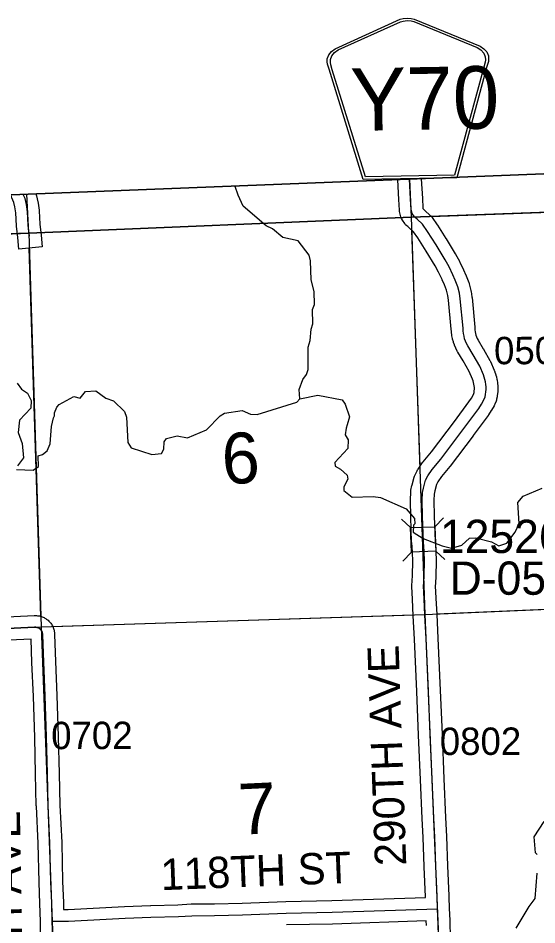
# Model space of a CAD drawing. Extents: x 128.7 to 185.5, y -21.4 to 12.6.
# Drawn here: x 151.741 to 153.067, y 3.118 to 5.436 of the extents above; entities that cross this region are included whole.
import ezdxf

# ---------------------------------------------------------------- set-up
doc = ezdxf.new("R2010")
doc.units = 0
for name, color, linetype in [('tdCoClipBndry', 7, 'Continuous'), ('tdCoCoBndry', 7, 'Continuous'), ('tdCoCoBndryPart', 7, 'Continuous'), ('tdCoHydroRiver', 7, 'Continuous'), ('tdCoSecRdNmbr', 7, 'Continuous'), ('tdCoSecRdTxt', 7, 'Continuous'), ('tdCoSecRteBand', 7, 'Continuous'), ('tdCoSecRteCL', 7, 'Continuous'), ('tdCoSectLine', 7, 'Continuous'), ('tdCoSectLinePart', 7, 'Continuous'), ('tdCoSectNmbr', 7, 'Continuous'), ('tdCoShieldCoRte', 7, 'Continuous'), ('tdCoStrucSec', 7, 'Continuous'), ('tdCoStrucSecCoName', 7, 'Continuous'), ('tdCoStrucSecFHWANum', 7, 'Continuous'), ('tdCoSurfGravel', 7, 'Continuous'), ('tdCoTwpBndry', 7, 'Continuous'), ('tdCoTwpBndryShd', 7, 'Continuous')]:
    doc.layers.add(name, color=color, linetype=linetype)

msp = doc.modelspace()

# ---------------------------------------------------------------- linework, layer by layer
at = {"layer": 'tdCoClipBndry'}
msp.add_lwpolyline([(134.0612, -7.7025), (133.8962, -2.6807), (133.6887, 4.3446), (133.6938, 4.3792), (133.7053, 4.4028), (133.7226, 4.4226), (133.7445, 4.4372), (133.7868, 4.4475), (134.771, 4.4649), (135.7559, 4.4935), (136.7866, 4.5129), (139.7725, 4.5879), (146.7594, 4.806), (147.7608, 4.8492), (149.7557, 4.9088), (150.75, 4.946), (153.7332, 5.0633)], dxfattribs=at)
at = {"layer": 'tdCoCoBndry'}
for p, q in [((152.7457, 4.9271), (153.7304, 4.9634)), ((153.7304, 4.9634), (152.7457, 4.9271)), ((151.7687, 4.8866), (152.7457, 4.9271)), ((152.7457, 4.9271), (151.7687, 4.8866)), ((150.7629, 4.8466), (151.7687, 4.8866)), ((151.7687, 4.8866), (150.7629, 4.8466))]:
    msp.add_line(p, q, dxfattribs=at)
for points in [[(153.7332, 5.0633), (150.75, 4.946), (149.7557, 4.9088), (147.7608, 4.8492), (146.7594, 4.806), (139.7725, 4.5879), (136.7866, 4.5129)], [(136.7888, 4.4129), (137.7724, 4.4375), (137.7858, 4.438), (138.7769, 4.4617), (139.7753, 4.488), (140.7687, 4.5163), (141.7663, 4.5476), (142.7677, 4.58), (143.7742, 4.6139), (144.7719, 4.6433), (145.7753, 4.6779), (146.7631, 4.7061), (147.7638, 4.7493), (148.7588, 4.7767), (149.759, 4.8089), (150.7538, 4.8461), (150.7626, 4.8466), (151.7683, 4.8866), (152.7453, 4.9271), (153.73, 4.9634)], [(136.7891, 4.4129), (137.7728, 4.4375), (137.7862, 4.438), (138.7773, 4.4617), (139.7757, 4.488), (140.769, 4.5163), (141.7667, 4.5476), (142.7681, 4.58), (143.7746, 4.6139), (144.7722, 4.6433), (145.7757, 4.6779), (146.7635, 4.7061), (147.7642, 4.7493), (148.7592, 4.7767), (149.7594, 4.8089), (150.7542, 4.8461), (150.7629, 4.8466), (151.7687, 4.8866), (152.7457, 4.9271), (153.7304, 4.9634)], [(136.7891, 4.4129), (137.7728, 4.4375), (137.7862, 4.438), (138.7773, 4.4617), (139.7757, 4.488), (140.769, 4.5163), (141.7667, 4.5476), (142.7681, 4.58), (143.7746, 4.6139), (144.7722, 4.6433), (145.7757, 4.6779), (146.7635, 4.7061), (147.7642, 4.7493), (148.7592, 4.7767), (149.7594, 4.8089), (150.7542, 4.8461), (150.7629, 4.8466), (151.7687, 4.8866), (152.7457, 4.9271), (153.7304, 4.9634)]]:
    msp.add_lwpolyline(points, dxfattribs=at)
at = {"layer": 'tdCoCoBndryPart'}
for points in [[(152.7968, 4.929), (153.73, 4.9634), (153.7375, 4.9634), (154.1359, 4.9808)], [(151.7989, 4.8879), (152.7199, 4.926)]]:
    msp.add_lwpolyline(points, dxfattribs=at)
at = {"layer": 'tdCoHydroRiver'}
for points in [[(152.4613, 4.4629), (152.4589, 4.4865), (152.4691, 4.5121), (152.4781, 4.525), (152.4824, 4.5378), (152.4821, 4.5946), (152.4878, 4.6122), (152.49, 4.6407), (152.4942, 4.655), (152.493, 4.6913), (152.4988, 4.7041), (152.4977, 4.7373), (152.4904, 4.767), (152.4887, 4.8159), (152.4851, 4.83), (152.457, 4.8669), (152.4172, 4.875), (152.3912, 4.8978), (152.3752, 4.9051), (152.3166, 4.9552), (152.303, 4.9832), (152.2955, 5.0058)], [(151.7384, 4.5029), (151.75, 4.4875), (151.7646, 4.477), (151.7747, 4.4584), (151.7738, 4.4394), (151.7448, 4.4084), (151.7412, 4.3767), (151.7516, 4.3486), (151.7544, 4.3124), (151.7393, 4.2914)], [(151.7365, 4.2818), (151.7792, 4.2801), (151.7931, 4.2901), (151.7922, 4.3169), (151.8031, 4.3204), (151.8154, 4.3303), (151.8227, 4.3479), (151.8259, 4.3922), (151.8315, 4.4145), (151.8344, 4.4194), (151.8342, 4.4272), (151.84, 4.4417), (151.8461, 4.4482), (151.8833, 4.4684), (151.8992, 4.4642), (151.9128, 4.482), (151.9396, 4.4829), (151.9655, 4.4649), (151.9847, 4.4576), (152.0125, 4.4302), (152.0177, 4.4161), (152.0215, 4.3516), (152.0298, 4.3376), (152.0825, 4.3205), (152.1077, 4.3229), (152.1136, 4.3342), (152.1146, 4.3532), (152.1206, 4.3613), (152.1472, 4.3685), (152.1742, 4.3631), (152.2225, 4.3837), (152.2575, 4.4196), (152.2684, 4.4263), (152.3139, 4.4326), (152.3348, 4.4238), (152.3522, 4.4228), (152.4537, 4.4547), (152.4613, 4.4629), (152.5068, 4.4723), (152.5688, 4.4602), (152.577, 4.4495), (152.5876, 4.4167), (152.582, 4.396), (152.5791, 4.388), (152.5766, 4.3705), (152.5849, 4.3582), (152.584, 4.336), (152.5505, 4.3002), (152.5509, 4.2907), (152.5653, 4.2833), (152.5816, 4.2681), (152.5836, 4.2571), (152.5732, 4.2378), (152.5735, 4.2283), (152.5946, 4.2117), (152.6482, 4.2135), (152.6673, 4.211), (152.733, 4.1817), (152.7543, 4.1572), (152.7548, 4.143), (152.7518, 4.1397), (152.7508, 4.1223), (152.7766, 4.1058), (152.8246, 4.0869), (152.8485, 4.0814), (152.8751, 4.0887), (152.895, 4.1067), (152.9108, 4.1072), (152.9506, 4.0976), (152.9699, 4.0872), (152.9902, 4.0942), (153.0113, 4.1217), (153.0216, 4.1442), (153.0182, 4.1978), (153.0318, 4.214), (153.0801, 4.2346)], [(153.0679, 3.298), (153.063, 3.3025), (153.06, 3.3435), (153.0855, 3.3823)], [(153.0143, 3.1099), (153.0472, 3.1647), (153.0622, 3.1857), (153.0679, 3.2506)]]:
    msp.add_lwpolyline(points, dxfattribs=at)
at = {"layer": 'tdCoSecRteBand'}
for points in [[(151.8574, 3.1575), (151.8691, 3.1576), (152.013, 3.1649), (152.0131, 3.1649), (152.0133, 3.165), (152.0794, 3.1677), (152.0796, 3.1677), (152.0799, 3.1677), (152.1493, 3.1694), (152.1832, 3.1716), (152.1841, 3.1716), (152.185, 3.1716), (152.2427, 3.1719), (152.3135, 3.1736), (152.425, 3.1778), (152.4252, 3.1778), (152.4255, 3.1778), (152.5427, 3.1803), (152.7821, 3.1881), (152.7821, 3.1897), (152.7786, 3.2667), (152.7786, 3.2668), (152.7786, 3.267), (152.7759, 3.3412), (152.7735, 3.3896), (152.7734, 3.3898), (152.7734, 3.3899), (152.7695, 3.489), (152.7646, 3.6031), (152.7646, 3.6032), (152.7646, 3.6032), (152.7599, 3.7144), (152.754, 3.8484), (152.7509, 3.9085), (152.7488, 3.9504), (152.7471, 3.9834), (152.747, 3.9854), (152.7471, 3.9875), (152.7479, 3.9959), (152.749, 4.0129), (152.7497, 4.0465), (152.7486, 4.0715), (152.7469, 4.095), (152.7468, 4.0956), (152.7468, 4.0961), (152.7446, 4.1612), (152.7446, 4.1614), (152.7446, 4.1615), (152.7436, 4.203), (152.7436, 4.2039), (152.7436, 4.2048), (152.7443, 4.2243), (152.7444, 4.2269), (152.745, 4.2294), (152.7474, 4.241), (152.7477, 4.242), (152.7479, 4.243), (152.7536, 4.2628), (152.7543, 4.2651), (152.7553, 4.2672), (152.7607, 4.2788), (152.7618, 4.2812), (152.7633, 4.2833), (152.7749, 4.2998), (152.7756, 4.3008), (152.7764, 4.3018), (152.7977, 4.3274), (152.8561, 4.4046), (152.8933, 4.4552), (152.8994, 4.4647), (152.9045, 4.4735), (152.9057, 4.4765), (152.9063, 4.4793), (152.9068, 4.4835), (152.9071, 4.4878), (152.9071, 4.492), (152.9067, 4.4963), (152.9061, 4.5005), (152.9052, 4.5047), (152.9039, 4.5088), (152.9023, 4.5131), (152.8939, 4.5328), (152.8785, 4.5598), (152.8646, 4.5823), (152.864, 4.5833), (152.8635, 4.5844), (152.8604, 4.5904), (152.86, 4.5913), (152.8595, 4.5923), (152.8569, 4.5985), (152.8565, 4.5995), (152.8562, 4.6005), (152.854, 4.6068), (152.8536, 4.6078), (152.8534, 4.6088), (152.8516, 4.6153), (152.8513, 4.6164), (152.8511, 4.6174), (152.8499, 4.624), (152.8497, 4.625), (152.8495, 4.6261), (152.8487, 4.6328), (152.8486, 4.6338), (152.8485, 4.6348), (152.8482, 4.641), (152.8414, 4.7151), (152.8396, 4.7266), (152.8362, 4.7404), (152.8308, 4.7543), (152.8247, 4.767), (152.8246, 4.7673), (152.8244, 4.7677), (152.8158, 4.7868), (152.8069, 4.8028), (152.7837, 4.8405), (152.7623, 4.874), (152.7518, 4.8896), (152.7405, 4.8996), (152.7367, 4.9031), (152.7345, 4.905), (152.7341, 4.9053), (152.7313, 4.9079), (152.7291, 4.9111), (152.7232, 4.92), (152.7206, 4.9239), (152.7193, 4.9285), (152.7166, 4.9381), (152.7156, 4.9414), (152.7155, 4.9449), (152.7143, 4.9721), (152.7116, 5.0231)], [(152.7715, 5.0255), (152.7742, 4.9752), (152.7742, 4.9751), (152.7742, 4.9749), (152.7753, 4.951), (152.7758, 4.9493), (152.7769, 4.9476), (152.7804, 4.9444), (152.7945, 4.9319), (152.7973, 4.9294), (152.7994, 4.9263), (152.8122, 4.9073), (152.8125, 4.9069), (152.8127, 4.9066), (152.8344, 4.8726), (152.8345, 4.8724), (152.8346, 4.8722), (152.8583, 4.8337), (152.8587, 4.8331), (152.859, 4.8326), (152.8689, 4.8148), (152.8695, 4.8137), (152.87, 4.8126), (152.8789, 4.7927), (152.8854, 4.7792), (152.886, 4.7781), (152.8864, 4.7769), (152.8928, 4.7601), (152.8935, 4.7585), (152.8939, 4.7567), (152.8981, 4.7399), (152.8984, 4.7387), (152.8986, 4.7374), (152.9009, 4.7236), (152.901, 4.7226), (152.9011, 4.7216), (152.908, 4.6459), (152.9081, 4.6453), (152.9081, 4.6447), (152.9084, 4.639), (152.909, 4.6344), (152.9098, 4.6299), (152.911, 4.6254), (152.9126, 4.621), (152.9144, 4.6167), (152.9164, 4.6127), (152.9299, 4.5908), (152.9301, 4.5904), (152.9303, 4.59), (152.9468, 4.5611), (152.9477, 4.5596), (152.9484, 4.558), (152.9578, 4.5361), (152.958, 4.5354), (152.9583, 4.5348), (152.9605, 4.5288), (152.9609, 4.5279), (152.9612, 4.5269), (152.963, 4.5207), (152.9633, 4.5197), (152.9635, 4.5187), (152.9649, 4.5125), (152.9651, 4.5115), (152.9653, 4.5104), (152.9662, 4.5041), (152.9664, 4.5031), (152.9665, 4.502), (152.967, 4.4957), (152.967, 4.4946), (152.967, 4.4936), (152.9671, 4.4872), (152.9671, 4.4862), (152.967, 4.4851), (152.9667, 4.4788), (152.9666, 4.4777), (152.9665, 4.4767), (152.9656, 4.4704), (152.9655, 4.4693), (152.9653, 4.4683), (152.964, 4.4621), (152.9635, 4.4596), (152.9626, 4.4572), (152.9596, 4.4496), (152.9588, 4.4473), (152.9575, 4.4452), (152.9509, 4.4339), (152.9506, 4.4334), (152.9503, 4.433), (152.9434, 4.4221), (152.9428, 4.4212), (152.9422, 4.4204), (152.9043, 4.3689), (152.9042, 4.3687), (152.904, 4.3686), (152.8451, 4.2906), (152.8447, 4.2901), (152.8443, 4.2896), (152.8233, 4.2644), (152.8139, 4.251), (152.8106, 4.2439), (152.8059, 4.2275), (152.8042, 4.2195), (152.8036, 4.2035), (152.8046, 4.1631), (152.8067, 4.0987), (152.8084, 4.0754), (152.8085, 4.075), (152.8085, 4.0746), (152.8097, 4.0482), (152.8098, 4.0472), (152.8097, 4.0462), (152.809, 4.011), (152.809, 4.0102), (152.8089, 4.0095), (152.8077, 3.9915), (152.8077, 3.9913), (152.8077, 3.991), (152.8071, 3.9844), (152.8087, 3.9535), (152.8087, 3.9534), (152.8087, 3.9534), (152.8108, 3.9116), (152.8139, 3.8513), (152.8139, 3.8512), (152.8139, 3.8511), (152.8198, 3.717), (152.8198, 3.7169), (152.8198, 3.7169), (152.8245, 3.6057), (152.8294, 3.4915), (152.8294, 3.4915), (152.8294, 3.4914), (152.8334, 3.3925), (152.8358, 3.3441), (152.8359, 3.3438), (152.8359, 3.3436), (152.8386, 3.2693), (152.842, 3.1922), (152.842, 3.192), (152.842, 3.1919), (152.8421, 3.1901), (152.8421, 3.19), (152.8421, 3.19), (152.8431, 3.1601), (152.8441, 3.1301), (152.8445, 3.1189), (152.8445, 3.1188), (152.8445, 3.1187), (152.846, 3.0677)], [(151.7431, 4.8455), (151.74, 4.8754), (151.7371, 4.904), (151.737, 4.9045), (151.737, 4.9051), (151.7348, 4.9385), (151.7329, 4.954), (151.7302, 4.9651), (151.725, 4.9771), (151.7245, 4.9782), (151.7241, 4.9794), (151.7225, 4.9842)], [(151.7862, 4.9868), (151.7863, 4.9865), (151.7873, 4.9842), (151.7879, 4.9817), (151.7916, 4.9664), (151.792, 4.9647), (151.7922, 4.963), (151.7945, 4.945), (151.7946, 4.9441), (151.7946, 4.9433), (151.7968, 4.9096), (151.7997, 4.8815), (151.8028, 4.8517), (151.7431, 4.8455)], [(151.6597, 3.9031), (151.7818, 3.9087), (151.7822, 3.9087), (151.7827, 3.9088), (151.7856, 3.9088), (151.7879, 3.9089), (151.7902, 3.9085), (151.7931, 3.9082), (151.7954, 3.9078), (151.7976, 3.9072), (151.8004, 3.9064), (151.8026, 3.9057), (151.8047, 3.9047), (151.8074, 3.9035), (151.8095, 3.9025), (151.8114, 3.9012), (151.8127, 3.9003), (151.8127, 3.9003), (151.8138, 3.8995), (151.8157, 3.8982), (151.8174, 3.8967), (151.8196, 3.8947), (151.8212, 3.8931), (151.8227, 3.8913), (151.8245, 3.889), (151.8259, 3.8872), (151.8271, 3.8852), (151.8285, 3.8826), (151.8296, 3.8806), (151.8305, 3.8784), (151.8315, 3.8757), (151.8323, 3.8735), (151.8328, 3.8713), (151.8334, 3.8684), (151.8339, 3.8661), (151.834, 3.8638), (151.8342, 3.8609), (151.8342, 3.8606), (151.8342, 3.8602), (151.8364, 3.7911), (151.8398, 3.7046), (151.8398, 3.7045), (151.8398, 3.7045), (151.8435, 3.5994), (151.8436, 3.5993), (151.8436, 3.5991), (151.8458, 3.5054), (151.8458, 3.5053), (151.8458, 3.5053), (151.8475, 3.4244), (151.8524, 3.3289), (151.8524, 3.3284), (151.8524, 3.3279), (151.8544, 3.229), (151.8569, 3.1756), (151.8569, 3.1753), (151.8569, 3.1751), (151.8574, 3.158), (151.8574, 3.1575)], [(151.7985, 3.0969), (151.7982, 3.1266), (151.7969, 3.1731), (151.7944, 3.2266), (151.7944, 3.227), (151.7944, 3.2274), (151.7925, 3.3263), (151.7876, 3.4217), (151.7875, 3.4222), (151.7875, 3.4226), (151.7858, 3.504), (151.7836, 3.5975), (151.7799, 3.7023), (151.7764, 3.7888), (151.7764, 3.7889), (151.7764, 3.789), (151.7745, 3.8483), (151.6623, 3.8431)], [(152.7845, 3.1169), (152.7842, 3.1281), (152.5445, 3.1203), (152.5443, 3.1203), (152.5441, 3.1203), (152.427, 3.1178)]]:
    msp.add_lwpolyline(points, dxfattribs=at)
at = {"layer": 'tdCoSecRteCL'}
for points in [[(152.8131, 3.1591), (152.812, 3.1909), (152.8086, 3.2681), (152.8059, 3.3425), (152.8034, 3.3911), (152.7995, 3.4903), (152.7945, 3.6044), (152.7899, 3.7157), (152.7839, 3.8498), (152.7809, 3.9101), (152.7788, 3.9519), (152.777, 3.9849), (152.7778, 3.9936), (152.779, 4.0116), (152.7797, 4.0468), (152.7785, 4.0732), (152.7768, 4.0972), (152.7746, 4.1623), (152.7736, 4.2037), (152.7743, 4.2232), (152.7768, 4.2348), (152.7825, 4.2545), (152.7879, 4.2661), (152.7995, 4.2826), (152.8212, 4.3087), (152.8801, 4.3867), (152.9181, 4.4382), (152.925, 4.4491), (152.9317, 4.4604), (152.9346, 4.468), (152.9359, 4.4743), (152.9367, 4.4806), (152.9371, 4.487), (152.9371, 4.4933), (152.9365, 4.4997), (152.9356, 4.506), (152.9342, 4.5122), (152.9324, 4.5183), (152.9302, 4.5243), (152.9208, 4.5462), (152.9043, 4.5751), (152.8902, 4.598), (152.8872, 4.604), (152.8845, 4.6102), (152.8823, 4.6166), (152.8806, 4.6231), (152.8793, 4.6297), (152.8785, 4.6364), (152.8781, 4.6431), (152.8712, 4.7188), (152.869, 4.7327), (152.8648, 4.7494), (152.8584, 4.7662), (152.8518, 4.78), (152.8426, 4.8002), (152.8328, 4.818), (152.8091, 4.8565), (152.7874, 4.8905), (152.7746, 4.9095), (152.7605, 4.922), (152.7566, 4.9255), (152.7544, 4.9274), (152.7541, 4.9277), (152.7482, 4.9366), (152.7455, 4.9462), (152.7442, 4.9736), (152.7416, 5.0243)], [(151.7699, 4.8784), (151.7669, 4.9071), (151.7647, 4.9413), (151.7625, 4.9593), (151.7588, 4.9746), (151.7541, 4.9855)], [(151.8282, 3.1272), (151.8269, 3.1742), (151.8244, 3.228), (151.8224, 3.3273), (151.8175, 3.4233), (151.8158, 3.5047), (151.8136, 3.5984), (151.8099, 3.7034), (151.8064, 3.79), (151.8042, 3.8593), (151.804, 3.8622), (151.8034, 3.8651), (151.8024, 3.8678), (151.801, 3.8704), (151.7991, 3.8727), (151.797, 3.8747), (151.7959, 3.8755), (151.7945, 3.8763), (151.7919, 3.8776), (151.7891, 3.8784), (151.7862, 3.8788), (151.7832, 3.8788), (151.6609, 3.8731)], [(151.8282, 3.1272), (151.87, 3.1276), (152.0145, 3.135), (152.0806, 3.1377), (152.1506, 3.1394), (152.1852, 3.1416), (152.2431, 3.1419), (152.3144, 3.1436), (152.4261, 3.1478), (152.5435, 3.1503), (152.8131, 3.1591)], [(152.8234, 2.9061), (152.8204, 2.9734), (152.816, 3.0666), (152.8145, 3.1179), (152.8131, 3.1591)], [(151.86, 2.3605), (151.8593, 2.381), (151.8571, 2.432), (151.8543, 2.4921), (151.8515, 2.5688), (151.8481, 2.6475), (151.8422, 2.7557), (151.838, 2.8509), (151.8355, 2.973), (151.8289, 3.1056), (151.8282, 3.1272)]]:
    msp.add_lwpolyline(points, dxfattribs=at)
at = {"layer": 'tdCoSectLine'}
for points in [[(152.7415, 5.0243), (152.7453, 4.9271)], [(151.7683, 4.8866), (151.7635, 4.9859)], [(152.7453, 4.9271), (153.73, 4.9634)], [(151.7683, 4.8866), (152.7453, 4.9271)], [(152.7453, 4.9271), (152.7804, 3.9118)], [(150.7626, 4.8466), (151.7683, 4.8866)], [(151.7683, 4.8866), (151.8001, 3.8798)], [(152.7804, 3.9118), (153.7687, 3.9538)], [(151.8001, 3.8798), (152.7804, 3.9118)], [(152.7804, 3.9118), (152.823, 2.9061)], [(150.7826, 3.8367), (151.8001, 3.8798)], [(151.8001, 3.8798), (151.8371, 2.8755)]]:
    msp.add_lwpolyline(points, dxfattribs=at)
at = {"layer": 'tdCoSectLinePart'}
for points in [[(152.7968, 4.929), (153.73, 4.9634)], [(151.7989, 4.8879), (152.7199, 4.926)], [(152.7465, 4.8943), (152.7674, 4.2895)], [(151.7695, 4.8483), (151.7993, 3.9062)], [(152.8104, 3.913), (153.7687, 3.9538)], [(151.8285, 3.8807), (152.7502, 3.9108)]]:
    msp.add_lwpolyline(points, dxfattribs=at)
at = {"layer": 'tdCoShieldCoRte'}
for points in [[(152.6227, 5.0239), (152.5359, 5.3053), (152.5318, 5.3184), (152.5309, 5.3243), (152.5308, 5.3321), (152.5349, 5.3425), (152.542, 5.3511), (152.5515, 5.3579), (152.7174, 5.4332), (152.7249, 5.435), (152.7353, 5.4361), (152.7458, 5.4353), (152.7533, 5.4338), (152.9218, 5.3644), (152.9315, 5.3579), (152.9389, 5.3495), (152.9434, 5.3393), (152.9435, 5.3315), (152.9429, 5.3256), (152.9392, 5.3124), (152.8622, 5.0281)], [(152.6285, 5.0303), (152.544, 5.3042), (152.54, 5.3167), (152.5392, 5.3224), (152.5391, 5.3299), (152.543, 5.3399), (152.5498, 5.3481), (152.5589, 5.3547), (152.7183, 5.4269), (152.7255, 5.4286), (152.7354, 5.4297), (152.7455, 5.429), (152.7527, 5.4275), (152.9145, 5.3609), (152.9238, 5.3546), (152.9309, 5.3466), (152.9351, 5.3368), (152.9353, 5.3293), (152.9347, 5.3236), (152.9312, 5.3109), (152.8563, 5.0343)]]:
    msp.add_lwpolyline(points, close=True, dxfattribs=at)
at = {"layer": 'tdCoStrucSec'}
for p, q in [((152.7438, 4.1336), (152.721, 4.155)), ((152.8064, 4.1357), (152.8278, 4.1586)), ((152.746, 4.071), (152.7246, 4.0482)), ((152.8085, 4.0732), (152.8314, 4.0518))]:
    msp.add_line(p, q, dxfattribs=at)
msp.add_lwpolyline([(152.746, 4.071), (152.7438, 4.1336), (152.8064, 4.1357), (152.8085, 4.0732)], close=True, dxfattribs=at)
at = {"layer": 'tdCoSurfGravel'}
for points in [[(152.7544, 4.9274), (152.7541, 4.9277), (152.7482, 4.9366), (152.7455, 4.9462), (152.7442, 4.9736), (152.7416, 5.0243)], [(151.7699, 4.8784), (151.7669, 4.9071), (151.7647, 4.9413), (151.7625, 4.9593), (151.7588, 4.9746), (151.7541, 4.9855)], [(152.7605, 4.922), (152.7566, 4.9255), (152.7544, 4.9274)], [(152.7809, 3.9101), (152.7788, 3.9519), (152.777, 3.9849), (152.7778, 3.9936), (152.779, 4.0116), (152.7797, 4.0468), (152.7785, 4.0732), (152.7768, 4.0972), (152.7746, 4.1623), (152.7736, 4.2037), (152.7743, 4.2232), (152.7768, 4.2348), (152.7825, 4.2545), (152.7879, 4.2661), (152.7995, 4.2826), (152.8212, 4.3087), (152.8801, 4.3867), (152.9181, 4.4382), (152.925, 4.4491), (152.9317, 4.4604), (152.9346, 4.468), (152.9359, 4.4743), (152.9367, 4.4806), (152.9371, 4.487), (152.9371, 4.4933), (152.9365, 4.4997), (152.9356, 4.506), (152.9342, 4.5122), (152.9324, 4.5183), (152.9302, 4.5243), (152.9208, 4.5462), (152.9043, 4.5751), (152.8902, 4.598), (152.8872, 4.604), (152.8845, 4.6102), (152.8823, 4.6166), (152.8806, 4.6231), (152.8793, 4.6297), (152.8785, 4.6364), (152.8781, 4.6431), (152.8712, 4.7188), (152.869, 4.7327), (152.8648, 4.7494), (152.8584, 4.7662), (152.8518, 4.78), (152.8426, 4.8002), (152.8328, 4.818), (152.8091, 4.8565), (152.7874, 4.8905), (152.7746, 4.9095), (152.7605, 4.922)], [(152.8234, 2.9061), (152.8204, 2.9734), (152.816, 3.0666), (152.8145, 3.1179), (152.8131, 3.1591), (152.812, 3.1909), (152.8086, 3.2681), (152.8059, 3.3425), (152.8034, 3.3911), (152.7995, 3.4903), (152.7945, 3.6044), (152.7899, 3.7157), (152.7839, 3.8498), (152.7809, 3.9101)], [(151.6609, 3.8731), (151.7832, 3.8788), (151.7862, 3.8788), (151.7891, 3.8784), (151.7919, 3.8776), (151.7945, 3.8763), (151.7959, 3.8755)], [(151.8289, 3.1056), (151.8282, 3.1272), (151.8269, 3.1742), (151.8244, 3.228), (151.8224, 3.3273), (151.8175, 3.4233), (151.8158, 3.5047), (151.8136, 3.5984), (151.8099, 3.7034), (151.8064, 3.79), (151.8042, 3.8593), (151.804, 3.8622), (151.8034, 3.8651), (151.8024, 3.8678), (151.801, 3.8704), (151.7991, 3.8727), (151.797, 3.8747), (151.7959, 3.8755)], [(151.8282, 3.1272), (151.87, 3.1276), (152.0145, 3.135), (152.0806, 3.1377), (152.1506, 3.1394), (152.1852, 3.1416), (152.2431, 3.1419), (152.3144, 3.1436), (152.4261, 3.1478), (152.5435, 3.1503), (152.8131, 3.1591)]]:
    msp.add_lwpolyline(points, dxfattribs=at)
at = {"layer": 'tdCoTwpBndry'}
msp.add_lwpolyline([(151.7992, 3.9066), (151.7695, 4.8483)], dxfattribs=at)
at = {"layer": 'tdCoTwpBndryShd'}
for points in [[(153.73, 4.9634), (152.7453, 4.9271), (151.7683, 4.8866), (150.7626, 4.8466), (150.7538, 4.8461), (149.759, 4.8089), (148.7588, 4.7767), (147.7638, 4.7493), (146.7631, 4.7061), (145.7753, 4.6779), (144.7719, 4.6433), (143.7742, 4.6139), (142.7677, 4.58), (141.7663, 4.5476), (140.7687, 4.5163), (139.7753, 4.488), (138.7769, 4.4617), (137.7858, 4.438), (137.7724, 4.4375), (136.7888, 4.4129)], [(151.7683, 4.8866), (151.8001, 3.8798), (151.8371, 2.8755), (151.8752, 1.8762), (151.9179, 0.8711), (151.9592, -0.1306), (152.001, -1.1385), (152.0322, -2.1463), (152.0609, -3.1441), (152.091, -4.1427), (152.1084, -4.6404), (153.0447, -4.6015), (153.5675, -4.583), (153.6062, -5.5939), (154.134, -5.5736), (154.1483, -6.0644), (155.1572, -6.0165), (155.1839, -7.0245), (155.1992, -7.5572), (156.1646, -7.5168), (157.1701, -7.4746), (158.2058, -7.4312)]]:
    msp.add_lwpolyline(points, dxfattribs=at)

# ---------------------------------------------------------------- texts
at = {"layer": 'tdCoSecRdNmbr'}
for s, rotation, p in [('0502', 0.1164, (152.9574, 4.5512)), ('0702', 0.1155, (151.8255, 3.5672)), ('0802', 0.1163, (152.8187, 3.5523))]:
    msp.add_text(s, height=0.07, rotation=rotation, dxfattribs=at).set_placement(p)
at = {"layer": 'tdCoSecRdTxt'}
for s, rotation, p in [('290TH AVE', 92, (152.7332, 3.27)), ('281TH AVE', 91, (151.7554, 2.846)), ('118TH ST', 2.2337, (152.1065, 3.2066))]:
    msp.add_text(s, height=0.08, rotation=rotation, dxfattribs=at).set_placement(p)
at = {"layer": 'tdCoSectNmbr'}
for s, p in [('6', (152.2643, 4.2443)), ('7', (152.3065, 3.3484))]:
    msp.add_text(s, height=0.13, rotation=2.6682, dxfattribs=at).set_placement(p)
at = {"layer": 'tdCoShieldCoRte'}
msp.add_text('Y70', height=0.16, rotation=1, dxfattribs=at).set_placement((152.5914, 5.1476))
at = {"layer": 'tdCoStrucSecCoName'}
msp.add_text('D-0507', height=0.085, dxfattribs=at).set_placement((152.844, 3.962))
at = {"layer": 'tdCoStrucSecFHWANum'}
msp.add_text('125261', height=0.085, dxfattribs=at).set_placement((152.819, 4.0687))

doc.saveas('drawing.dxf')
